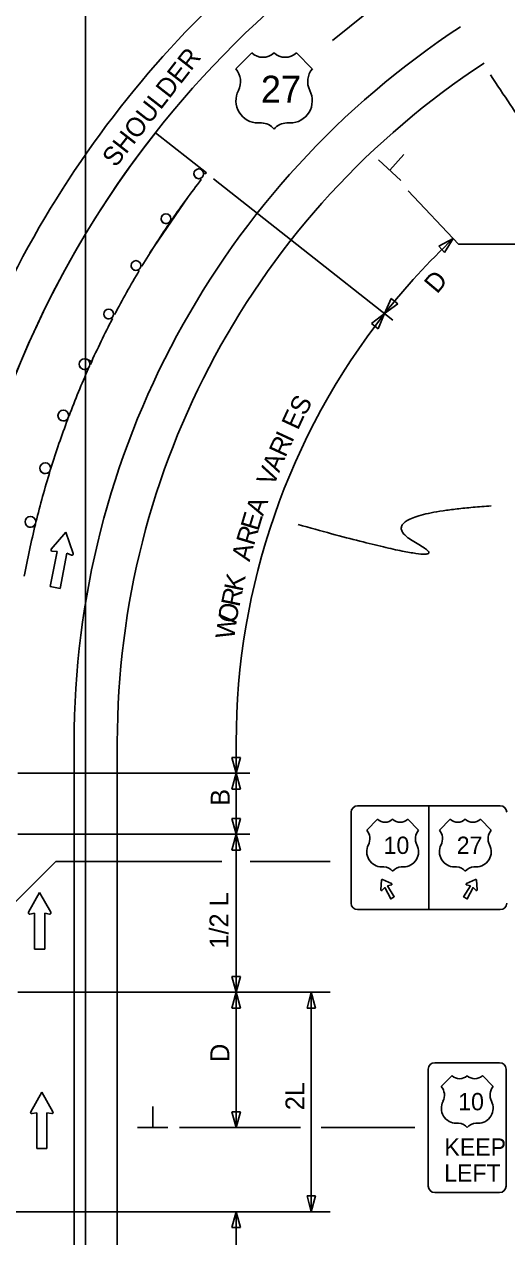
# Model space of a CAD drawing. Extents: x 16630 to 19509, y 5576 to 6998.
# Drawn here: x 16981.9 to 17160.6, y 6297.8 to 6745.9 of the extents above; entities that cross this region are included whole.
import ezdxf

# ---------------------------------------------------------------- set-up
doc = ezdxf.new("R2010")
doc.units = 0
for name, color, linetype in [('ALI_LEGAL_EX', 7, 'Continuous'), ('MT_SCRATCH_LEVEL_A', 7, 'Continuous'), ('MT_SCRATCH_LEVEL_E', 7, 'Continuous'), ('PAVT_EDGE_EX', 7, 'Continuous'), ('TRAFFIC_SIGNS_PR', 7, 'Continuous'), ('TYPICAL_EX', 7, 'Continuous'), ('TYPICAL_TEXT_DIMEN_PR', 7, 'Continuous')]:
    doc.layers.add(name, color=color, linetype=linetype)

msp = doc.modelspace()

# ---------------------------------------------------------------- linework, layer by layer
at = {"layer": 'ALI_LEGAL_EX'}
for p, q in [((17004.68, 6974.12), (17004.68, 6155.98)), ((17004.68, 6922.21), (17004.68, 6058.3))]:
    msp.add_line(p, q, dxfattribs=at)
for points in [[(17096.1, 6739.95), (17115.56, 6755.65)], [(17028.47, 6661.47), (17042.59, 6682.1)], [(17028.47, 6661.47), (17042.59, 6682.1)]]:
    msp.add_lwpolyline(points, dxfattribs=at)
at = {"layer": 'MT_SCRATCH_LEVEL_A'}
for points in [[(17049.36, 6690.98), (17030.51, 6705.83)], [(17047.47, 6688.56), (17047.02, 6688.91)], [(17048.36, 6690.77), (17049.21, 6690.79)], [(17036.22, 6674.06), (17036.65, 6673.76)], [(17035.5, 6672.09), (17035.08, 6672.38)], [(17025.1, 6656.76), (17025.49, 6656.52)], [(17024.54, 6654.94), (17024.15, 6655.17)], [(17015.04, 6638.82), (17015.4, 6638.63)], [(17014.63, 6637.16), (17014.27, 6637.35)], [(17006.27, 6620.31), (17006.43, 6620.24)], [(17005.76, 6618.76), (17005.6, 6618.83)], [(16998.06, 6599.94), (16997.94, 6599.98)], [(16998.43, 6601.3), (16998.55, 6601.25)], [(16991.49, 6580.69), (16991.4, 6580.72)], [(16991.75, 6581.84), (16991.84, 6581.82)], [(16986.25, 6562.02), (16986.31, 6562.01)], [(16986.08, 6561.09), (16986.02, 6561.1)], [(16981.95, 6541.91), (16981.99, 6541.9)]]:
    msp.add_lwpolyline(points, dxfattribs=at)
for centre, radius, start, end in [((17316.4, 6480.53), 364, 141.7598, 180), ((17046.56, 6690.66), 1.8, 3.5129, 180), ((17316.4, 6480.53), 340, 142.2759, 145.3661), ((17046.56, 6690.66), 1.8, 180, 284.5518), ((17316.4, 6480.53), 340, 141.7598, 141.7992), ((17034.42, 6674.06), 1.8, 0, 180), ((17034.42, 6674.06), 1.8, 180, 291.4148), ((17316.4, 6480.53), 340, 145.7074, 148.8275), ((17023.3, 6656.76), 1.8, 0, 180), ((17023.3, 6656.76), 1.8, 180, 298.2766), ((17316.4, 6480.53), 340, 149.1383, 152.2895), ((17013.24, 6638.82), 1.8, 0, 180), ((17013.24, 6638.82), 1.8, 180, 305.1374), ((17316.4, 6480.53), 340, 152.5687, 155.7382), ((17004.27, 6620.31), 2, 0, 180), ((17004.27, 6620.31), 2, 180, 312.0242), ((17316.4, 6480.53), 340, 156.0121, 159.2032), ((16996.43, 6601.3), 2, 0, 180), ((17316.4, 6480.53), 340, 159.4399, 162.6687), ((16996.43, 6601.3), 2, 180, 318.8797), ((16989.75, 6581.84), 2, 0, 180), ((17316.4, 6480.53), 340, 162.8672, 166.1345), ((16989.75, 6581.84), 2, 180, 325.7344), ((16984.25, 6562.02), 2, 0, 180), ((16984.25, 6562.02), 2, 180, 332.5884), ((17316.4, 6480.53), 340, 166.2942, 169.6006)]:
    msp.add_arc(centre, radius, start, end, dxfattribs=at)
at = {"layer": 'MT_SCRATCH_LEVEL_E'}
for p, q in [((16997.4, 6558.21), (16991.97, 6551.9)), ((17000.07, 6550.31), (16997.4, 6558.21)), ((16994.11, 6551.1), (16991.55, 6538.09)), ((16992.31, 6551.13), (16994.11, 6551.1)), ((16995.23, 6537.37), (16997.78, 6550.38)), ((16997.78, 6550.38), (16999.47, 6549.73)), ((16991.55, 6538.09), (16995.23, 6537.37)), ((16987.65, 6424.96), (16983.54, 6417.72)), ((16991.8, 6417.72), (16987.65, 6424.96)), ((16984.02, 6417.03), (16985.8, 6417.35)), ((16985.8, 6417.35), (16985.8, 6404.09)), ((16989.54, 6404.09), (16989.54, 6417.35)), ((16989.54, 6417.35), (16991.32, 6417.03)), ((16985.8, 6404.09), (16989.54, 6404.09)), ((16988.45, 6351.23), (16984.34, 6343.99)), ((16992.6, 6343.99), (16988.45, 6351.23)), ((16984.82, 6343.31), (16986.6, 6343.62)), ((16986.6, 6343.62), (16986.6, 6330.36)), ((16990.34, 6330.36), (16990.34, 6343.62)), ((16990.34, 6343.62), (16992.12, 6343.31)), ((16986.6, 6330.36), (16990.34, 6330.36))]:
    msp.add_line(p, q, dxfattribs=at)
for centre, start, end in [((16992.32, 6551.6), 139.3091, 268.8481), ((16999.62, 6550.16), 248.9205, 18.6574), ((16983.95, 6417.49), 150.4248, 279.9638), ((16991.39, 6417.49), 260.0362, 29.7731), ((16984.75, 6343.76), 150.4248, 279.9638), ((16992.19, 6343.76), 260.0362, 29.7731)]:
    msp.add_arc(centre, 0.463, start, end, dxfattribs=at)
at = {"layer": 'PAVT_EDGE_EX'}
for p, q in [((17000.4, 6480.53), (17000.4, 6125.9)), ((17016.4, 6480.53), (17016.4, 6125.9))]:
    msp.add_line(p, q, dxfattribs=at)
for radius, start, end in [(380, 123.1879, 163.0483), (364, 123.1879, 180), (316, 123.1879, 180), (300, 123.1879, 180), (300, 180, 180.00000277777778)]:
    msp.add_arc((17316.4, 6480.53), radius, start, end, dxfattribs=at)
at = {"layer": 'TRAFFIC_SIGNS_PR'}
for p, q in [((17102.95, 6454.67), (17102.95, 6421.07)), ((17105.35, 6457.07), (17158.15, 6457.07)), ((17131.75, 6457.07), (17131.75, 6418.67)), ((17113.93, 6426.02), (17114.22, 6429.65)), ((17114.59, 6429.86), (17117.87, 6428.3)), ((17148.92, 6429.86), (17145.64, 6428.3)), ((17149.57, 6426.02), (17149.29, 6429.65)), ((17105.35, 6418.67), (17158.15, 6418.67)), ((17131.51, 6359.71), (17131.51, 6316.51)), ((17157.91, 6362.11), (17133.91, 6362.11)), ((17160.31, 6316.51), (17160.31, 6359.71)), ((17133.91, 6314.11), (17157.91, 6314.11))]:
    msp.add_line(p, q, dxfattribs=at)
for points in [[(17117.83, 6427.81), (17116.42, 6427.42), (17118.93, 6423.44), (17117.6, 6422.67), (17115.41, 6426.84), (17114.37, 6425.82)], [(17145.68, 6427.81), (17147.09, 6427.42), (17144.57, 6423.44), (17145.9, 6422.67), (17148.09, 6426.84), (17149.13, 6425.82)]]:
    msp.add_lwpolyline(points, dxfattribs=at)
for centre, radius in [((17046.56, 6690.66), 1.8), ((17034.42, 6674.06), 1.8), ((17023.3, 6656.76), 1.8), ((17013.24, 6638.82), 1.8), ((17004.27, 6620.31), 2), ((16996.43, 6601.3), 2), ((16989.75, 6581.84), 2), ((16984.25, 6562.02), 2)]:
    msp.add_circle(centre, radius, dxfattribs=at)
for centre, radius, start, end in [((17105.35, 6454.67), 2.4, 90, 180), ((17105.35, 6454.67), 2.4, 90, 180), ((17158.15, 6454.67), 2.4, 0, 90), ((17114.47, 6429.63), 0.26, 64.4823, 175.5177), ((17117.75, 6428.06), 0.26, 285.9885, 64.4823), ((17145.75, 6428.06), 0.26, 115.5177, 254.0115), ((17149.03, 6429.63), 0.26, 4.4823, 115.5177), ((17114.19, 6426), 0.26, 175.5177, 314.0115), ((17149.31, 6426), 0.26, 225.9885, 4.4823), ((17105.35, 6421.07), 2.4, 180, 270), ((17158.15, 6421.07), 2.4, 270, 0), ((17133.91, 6359.71), 2.4, 90, 180), ((17157.91, 6359.71), 2.4, 0, 90), ((17133.91, 6316.51), 2.4, 180, 270), ((17157.91, 6316.51), 2.4, 270, 0)]:
    msp.add_arc(centre, radius, start, end, dxfattribs=at)
at = {"layer": 'TYPICAL_EX'}
for p, q in [((17060.28, 6729.51), (17066.18, 6735.4)), ((17088.58, 6729.51), (17082.68, 6735.4)), ((17068.53, 6709.45), (17069.71, 6709.45)), ((17080.33, 6709.45), (17079.15, 6709.45)), ((17108.7, 6448.07), (17112.7, 6452.07)), ((17127.9, 6448.07), (17123.9, 6452.07)), ((17135.6, 6448.07), (17139.6, 6452.07)), ((17154.8, 6448.07), (17150.8, 6452.07)), ((17114.3, 6434.46), (17115.1, 6434.46)), ((17122.31, 6434.46), (17121.51, 6434.46)), ((17141.2, 6434.46), (17142, 6434.46)), ((17149.21, 6434.46), (17148.41, 6434.46)), ((17136.31, 6353.31), (17140.31, 6357.31)), ((17155.51, 6353.31), (17151.51, 6357.31)), ((17141.91, 6339.7), (17142.71, 6339.7)), ((17149.92, 6339.7), (17149.12, 6339.7))]:
    msp.add_line(p, q, dxfattribs=at)
for centre, radius, start, end in [((17070.3, 6739.69), 5.96, 226.1404, 313.8596), ((17078.56, 6739.69), 5.96, 226.1404, 313.8596), ((17054.69, 6724.78), 7.31, 333.0977, 40.1936), ((17094.17, 6724.78), 7.31, 139.8064, 206.9023), ((17068.54, 6717.69), 8.24, 152.6698, 269.9013), ((17080.32, 6717.69), 8.24, 270.0987, 27.3302), ((17069.72, 6703.54), 5.91, 37.1038, 90.1385), ((17079.14, 6703.54), 5.91, 89.8615, 142.8962), ((17115.5, 6454.99), 4.04, 226.1404, 313.8596), ((17121.1, 6454.99), 4.04, 226.1404, 313.8596), ((17142.4, 6454.99), 4.04, 226.1404, 313.8596), ((17148, 6454.99), 4.04, 226.1404, 313.8596), ((17104.91, 6444.87), 4.96, 333.0977, 40.1936), ((17131.69, 6444.87), 4.96, 139.8064, 206.9023), ((17131.81, 6444.87), 4.96, 333.0977, 40.1936), ((17158.59, 6444.87), 4.96, 139.8064, 206.9023), ((17114.31, 6440.06), 5.59, 152.6698, 269.9013), ((17122.3, 6440.06), 5.59, 270.0987, 27.3302), ((17141.21, 6440.06), 5.59, 152.6698, 269.9013), ((17149.2, 6440.06), 5.59, 270.0987, 27.3302), ((17115.11, 6430.46), 4.01, 37.1038, 90.1385), ((17121.5, 6430.46), 4.01, 89.8615, 142.8962), ((17142.01, 6430.46), 4.01, 37.1038, 90.1385), ((17148.4, 6430.46), 4.01, 89.8615, 142.8962), ((17143.11, 6360.22), 4.04, 226.1404, 313.8596), ((17148.71, 6360.22), 4.04, 226.1404, 313.8596), ((17132.52, 6350.11), 4.96, 333.0977, 40.1936), ((17159.3, 6350.11), 4.96, 139.8064, 206.9023), ((17141.92, 6345.29), 5.59, 152.6698, 269.9013), ((17149.91, 6345.29), 5.59, 270.0987, 27.3302), ((17142.72, 6335.69), 4.01, 37.1038, 90.1385), ((17149.11, 6335.69), 4.01, 89.8615, 142.8962)]:
    msp.add_arc(centre, radius, start, end, dxfattribs=at)
at = {"layer": 'TYPICAL_TEXT_DIMEN_PR'}
for p, q in [((17121.33, 6688.23), (17113.09, 6695.89)), ((17117.21, 6692.06), (17122.51, 6697.77)), ((17052.06, 6688.84), (17118.33, 6636.62)), ((17124.09, 6684.37), (17142.7, 6664.64)), ((17135.38, 6663.86), (17140.72, 6666.74)), ((17140.72, 6666.74), (17137.53, 6661.57)), ((17142.7, 6664.64), (17175.9, 6664.64)), ((17142.7, 6664.64), (17175.9, 6664.64)), ((17142.7, 6664.64), (17175.9, 6664.64)), ((17136.46, 6662.71), (17135.38, 6663.86)), ((17137.53, 6661.57), (17136.46, 6662.71)), ((17115.33, 6638.99), (17117.73, 6644.56)), ((17120.19, 6642.62), (17115.33, 6638.99)), ((17117.73, 6644.56), (17118.96, 6643.59)), ((17118.96, 6643.59), (17120.19, 6642.62)), ((17110.47, 6635.35), (17115.33, 6638.99)), ((17115.33, 6638.99), (17112.94, 6633.41)), ((17111.7, 6634.38), (17110.47, 6635.35)), ((17112.94, 6633.41), (17111.7, 6634.38)), ((17006.91, 6621.31), (17005.09, 6622.14)), ((17060.4, 6480.53), (17060.4, 6469.09)), ((17060.4, 6469.09), (17058.83, 6474.95)), ((17058.83, 6474.95), (17060.4, 6474.95)), ((17060.4, 6474.95), (17061.97, 6474.95)), ((17061.97, 6474.95), (17060.4, 6469.09)), ((16979.6, 6469.09), (17065.4, 6469.09)), ((17058.83, 6463.22), (17060.4, 6469.09)), ((17060.4, 6469.09), (17060.4, 6446.53)), ((17060.4, 6469.09), (17061.97, 6463.22)), ((17060.4, 6463.22), (17058.83, 6463.22)), ((17061.97, 6463.22), (17060.4, 6463.22)), ((17060.4, 6446.53), (17058.83, 6452.39)), ((17058.83, 6452.39), (17060.4, 6452.39)), ((17060.4, 6452.39), (17061.97, 6452.39)), ((17061.97, 6452.39), (17060.4, 6446.53)), ((16979.6, 6446.53), (17065.4, 6446.53)), ((17058.83, 6440.67), (17060.4, 6446.53)), ((17060.4, 6446.53), (17060.4, 6388.14)), ((17060.4, 6446.53), (17061.97, 6440.67)), ((17060.4, 6440.67), (17058.83, 6440.67)), ((17061.97, 6440.67), (17060.4, 6440.67)), ((16970.24, 6413.2), (16993.65, 6436.53)), ((17055.09, 6436.53), (16993.65, 6436.53)), ((17065.63, 6436.53), (17095.19, 6436.53)), ((17060.4, 6388.14), (17058.83, 6394)), ((17058.83, 6394), (17060.4, 6394)), ((17060.4, 6394), (17061.97, 6394)), ((17061.97, 6394), (17060.4, 6388.14)), ((17095.19, 6388.14), (16979.6, 6388.14)), ((17058.83, 6382.28), (17060.4, 6388.14)), ((17060.4, 6388.14), (17061.97, 6382.28)), ((17060.4, 6388.14), (17060.4, 6338.14)), ((17086.64, 6382.28), (17088.21, 6388.14)), ((17088.21, 6388.14), (17088.21, 6307.03)), ((17088.21, 6388.14), (17089.78, 6382.28)), ((17060.4, 6382.28), (17058.83, 6382.28)), ((17061.97, 6382.28), (17060.4, 6382.28)), ((17088.21, 6382.28), (17086.64, 6382.28)), ((17089.78, 6382.28), (17088.21, 6382.28)), ((17029.53, 6338.14), (17029.53, 6345.93)), ((17060.4, 6338.14), (17058.83, 6344)), ((17058.83, 6344), (17060.4, 6344)), ((17060.4, 6344), (17061.97, 6344)), ((17061.97, 6344), (17060.4, 6338.14)), ((17035.15, 6338.14), (17023.9, 6338.14)), ((17084.21, 6338.14), (17039.4, 6338.14)), ((17126.54, 6338.14), (17091.83, 6338.14)), ((17088.21, 6307.03), (17086.64, 6312.89)), ((17086.64, 6312.89), (17088.21, 6312.89)), ((17088.21, 6312.89), (17089.78, 6312.89)), ((17089.78, 6312.89), (17088.21, 6307.03)), ((16955.45, 6307.03), (17095.19, 6307.03)), ((17058.83, 6301.17), (17060.4, 6307.03)), ((17060.4, 6278.47), (17060.4, 6307.03)), ((17060.4, 6307.03), (17061.97, 6301.17)), ((17060.4, 6301.17), (17058.83, 6301.17)), ((17061.97, 6301.17), (17060.4, 6301.17))]:
    msp.add_line(p, q, dxfattribs=at)
for start, end in [(133.334, 141.7597), (141.7599, 180)]:
    msp.add_arc((17316.4, 6480.53), 256, start, end, dxfattribs=at)
for points in [[(17154.48, 6727.28), (17192.72, 6669.11), (17169.5, 6734.81), (17198.86, 6725.23)], [(17083.35, 6560.99), (17146.59, 6543.42), (17107.77, 6564.76), (17154.73, 6567.9)]]:
    msp.add_open_spline(points, degree=2, dxfattribs=at)

# ---------------------------------------------------------------- texts
at = {"layer": 'TRAFFIC_SIGNS_PR'}
for s, p in [('10', (17114.96, 6439.27)), ('27', (17142.03, 6439.27)), ('10', (17142.57, 6344.51)), ('KEEP', (17137.45, 6327.71)), ('LEFT', (17137.36, 6318.11))]:
    msp.add_text(s, height=6.4, dxfattribs=at).set_placement(p)
at = {"layer": 'TYPICAL_EX'}
msp.add_text('27', height=10, dxfattribs=at).set_placement((17069.54, 6716.93))
at = {"layer": 'TYPICAL_TEXT_DIMEN_PR'}
for s, rotation, p in [('SHOULDER', 52.0184, (17015.76, 6692.73)), ('D', 50, (17134.74, 6646.01)), ('S', 62.4974, (17085.93, 6600.91)), ('E', 65.1772, (17083.24, 6595.61)), ('R', 65.1772, (17078.58, 6585.54)), ('I', 65.1772, (17081.08, 6590.96)), ('A', 67.857, (17076.3, 6579.94)), ('V', 67.857, (17074.2, 6574.78)), ('A', 70.5368, (17070.32, 6563.9)), ('E', 73.2167, (17068.57, 6558.32)), ('R', 73.2167, (17066.95, 6552.92)), ('A', 75.8965, (17065.37, 6547.08)), ('K', 78.5763, (17062.72, 6535.95)), ('R', 78.5763, (17061.58, 6530.32)), ('O', 81.2562, (17060.5, 6524.36)), ('W', 81.2562, (17059.57, 6518.33)), ('B', 90, (17057.97, 6457.04)), ('1/2 L', 90, (17057.54, 6404.27)), ('D', 90, (17057.84, 6362.36)), ('2L', 90, (17085.65, 6344.53))]:
    msp.add_text(s, height=7, rotation=rotation, dxfattribs=at).set_placement(p)

doc.saveas('drawing.dxf')
